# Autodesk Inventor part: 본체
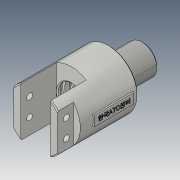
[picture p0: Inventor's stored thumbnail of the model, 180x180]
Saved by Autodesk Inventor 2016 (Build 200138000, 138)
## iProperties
Created: 2019-02
Part Number: 본체
Material: 알루미늄 6061
Document SubType Name: Modeling
Designer: Administrator
Density: 2.7 g/cm^3
Appearance: 알루미늄 - 평지
Mass: 345.889 g
Surface Area: 290.427 cm^2
Volume: 128.107 cm^3
Author: Administrator
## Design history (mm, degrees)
sketch "스케치1"
  geometry: C1 r 29 at (0, 0); 1 further point
  constraints: 1 centre point, 1 coincident
  dimensions: "d0" = 58 diameter of C1
extrude "돌출1" new body sketch "스케치1" distance "d1" = 74; taper "d2" = 0 deg
sketch "스케치2"
  geometry: C1 r 13 at (0, 0); 1 further point
  constraints: 1 centre point, 1 coincident
  dimensions: "d3" = 26 diameter of C1
extrude "돌출2" join sketch "스케치2" distance "d4" = 5; taper "d5" = 0 deg
sketch "스케치3"
  geometry: C1 r 15 at (0, 0); 1 further point
  constraints: 1 centre point, 1 coincident
  dimensions: "d6" = 30 diameter of C1
extrude "돌출3" join sketch "스케치3" distance "d7" = 29; taper "d8" = 0 deg
feature "스레드1" dims "d9" = 10, "d10" = 0
node "작업 평면1"
sketch "스케치4"
  geometry: L1 (15, -36)-(-15, -36); L2 (-15, -36)-(-15, 0); L3 (-15, 0)-(15, 0); L4 (15, 0)-(15, -36); 2 further points
  constraints: 8 end point, 2 coincident, 2 parallel, 1 horizontal, 1 midpoint, 1 perpendicular
  dimensions: "d12" = 30 distance of L2.end L3.end; "d13" = 36 distance of L1.end L2.end
extrude "돌출4" cut sketch "스케치4" stored distance "d14" = 59; taper "d15" = 0 deg
sketch "스케치5"
  geometry: L1 (29, -16)-(22, -16); L2 (22, -16)-(22, 0); L3 (22, 0)-(29, 0); L4 (29, 0)-(29, -16); L5 (-22, -16)-(-29, -16); L6 (-29, -16)-(-29, 0); L7 (-29, 0)-(-22, 0); L8 (-22, 0)-(-22, -16); L9 (15, -36)-(15, 0) reference; L10 (15, 0)-(15, 0) reference; L11 (15, 0)-(15, -36) reference; L12 (15, -36)-(-15, -36) reference; L13 (-15, -36)-(-15, 0) reference; L14 (-15, 0)-(-15, 0) reference; L15 (-15, 0)-(-15, -36) reference; L16 (-15, -36)-(15, -36) reference; L17 (-29, -74)-(29, -74) reference; L18 (15, 0)-(29, 0) reference; L19 (29, 0)-(29, -74) reference; L20 (-29, 0)-(-15, 0) reference; L21 (-29, 0)-(-29, -74) reference; 1 further point
  constraints: 16 end point, 5 parallel, 4 coincident, 2 horizontal, 2 perpendicular
  dimensions: "d16" = 7 distance of L2.end L3.end; "d17" = 16 distance of L3.end L1.start; "d18" = 7 distance of L6.end L7.end
extrude "돌출5" cut sketch "스케치5" stored distance "d19" = 0; taper "d20" = 0 deg
sketch "스케치6"
  geometry: L1 (16, 0)-(16, 37.789) reference; L2 (0, 37.789)-(16, 37.789) reference; L3 (0, 0)-(0, 37.789) reference; L4 (16, 0)-(0, 0) reference; L5 (74, 0)-(16, 0) reference; L6 (74, 37.789)-(74, 0) reference; L7 (16, 37.789)-(74, 37.789) reference; C1 r 3 at (9, 27.894); C2 r 3 at (9, 9.894); 1 further point
  constraints: 2 centre point, 1 vertical alignment
  dimensions: "d21" = 6 diameter of C1; "d22" = 6 diameter of C2; "d23" = 18 distance of C2.centre C1.centre; "d24" = 9 horizontal distance of C2.centre point (0, 18.894); "d25" = 9 horizontal distance of C1.centre point (0, 18.894)
extrude "돌출6" cut sketch "스케치6" stored distance "d27" = 59; taper "d28" = 0 deg
sketch "스케치8"
  geometry: C1 r 14 at (0, 0); 1 further point
  constraints: 1 centre point, 1 coincident
  dimensions: "d37" = 28 diameter of C1
extrude "돌출7" cut sketch "스케치8" distance "d38" = 2.65; taper "d39" = 0 deg
sketch "스케치10"
  geometry: C1 r 17 at (0, 0); 1 further point
  constraints: 1 centre point, 1 coincident
  dimensions: "d41" = 34 diameter of C1
extrude "돌출8" cut sketch "스케치10" distance "d42" = 4.7; taper "d43" = 0 deg
sketch "스케치11"
  geometry: C1 r 14 at (0, 0); 1 further point
  constraints: 1 centre point, 1 coincident
  dimensions: "d44" = 28 diameter of C1
extrude "돌출9" cut sketch "스케치11" distance "d45" = 4.3; taper "d46" = 0 deg
sketch "스케치12"
  geometry: C1 r 17 at (0, 0); 1 further point
  constraints: 1 centre point, 1 coincident
  dimensions: "d47" = 34 diameter of C1
extrude "돌출10" cut sketch "스케치12" distance "d48" = 4.7; taper "d49" = 0 deg
sketch "스케치15"
  geometry: C1 r 14 at (0, 0); 1 further point
  constraints: 1 centre point, 1 coincident
  dimensions: "d56" = 28 diameter of C1
extrude "돌출13" cut sketch "스케치15" distance "d57" = 3.65; taper "d58" = 0 deg
sketch "스케치16"
  geometry: C1 r 16 at (0, 0); 1 further point
  constraints: 1 centre point, 1 coincident
  dimensions: "d59" = 32 diameter of C1
extrude "돌출14" cut sketch "스케치16" distance "d60" = 7; taper "d61" = 0 deg
hole "구멍1" diameter "d64" = 8; stored, may be unused: countersink angle "d68" = 90 deg, drill point angle "d70" = 118 deg; dims "d62" = 10, "d63" = 10, "d65" = 6, "d66" = 4, "d67" = 2, "d69" = 8
hole "구멍2" diameter "d73" = 12.376; stored, may be unused: countersink angle "d77" = 90 deg, drill point angle "d79" = 118 deg; dims "d71" = 10, "d72" = 10, "d74" = 18, "d75" = 4, "d76" = 2, "d78" = 22
node "작업 평면3"
sketch "스케치17"
  geometry: L1 (5, -29)-(-5, -29); L2 (-5, -29)-(-5, -69); L3 (-5, -69)-(5, -69); L4 (5, -69)-(5, -29); L5 (-29, -74)-(29, -74) reference; 2 further points
  constraints: 8 end point, 2 parallel, 1 horizontal, 1 midpoint, 1 perpendicular, 1 vertical alignment
  dimensions: "d82" = 40 distance of L3.end L1.start; "d83" = 10 distance of L1.start L1.end; "d84" = 5 distance between parallel lines of L5 L3
extrude "돌출15" join sketch "스케치17" stored distance "d85" = 7; taper "d86" = 0 deg
sketch "스케치18"
  geometry: L1 (29, 5)-(69, 5) reference; L2 (29, 5)-(29, -5) reference; 4 further points
  constraints: 2 midpoint, 1 horizontal alignment, 1 vertical alignment, 1 other
feature "엠보싱1" sketch "스케치18" dims "d1" = 74, "d12" = 30, "d13" = 36, "d87" = 0.5, "d88" = 0
chamfer "모따기1" distance "d89" = 1; stored, may be unused: second distance "d90" = 2, angle "d91" = 45 deg
chamfer "모따기2" distance "d92" = 1; stored, may be unused: second distance "d93" = 2, angle "d94" = 45 deg
chamfer "모따기3" distance "d95" = 1; stored, may be unused: second distance "d96" = 2, angle "d97" = 45 deg
chamfer "모따기4" distance "d98" = 1; stored, may be unused: second distance "d99" = 2, angle "d100" = 45 deg
fillet "모깎기1" dims "d101" = 0.8
node "솔리드1"
node "투영된 루프1"
node "절단 모서리 투영1"
other parameters: "d11" = 29
